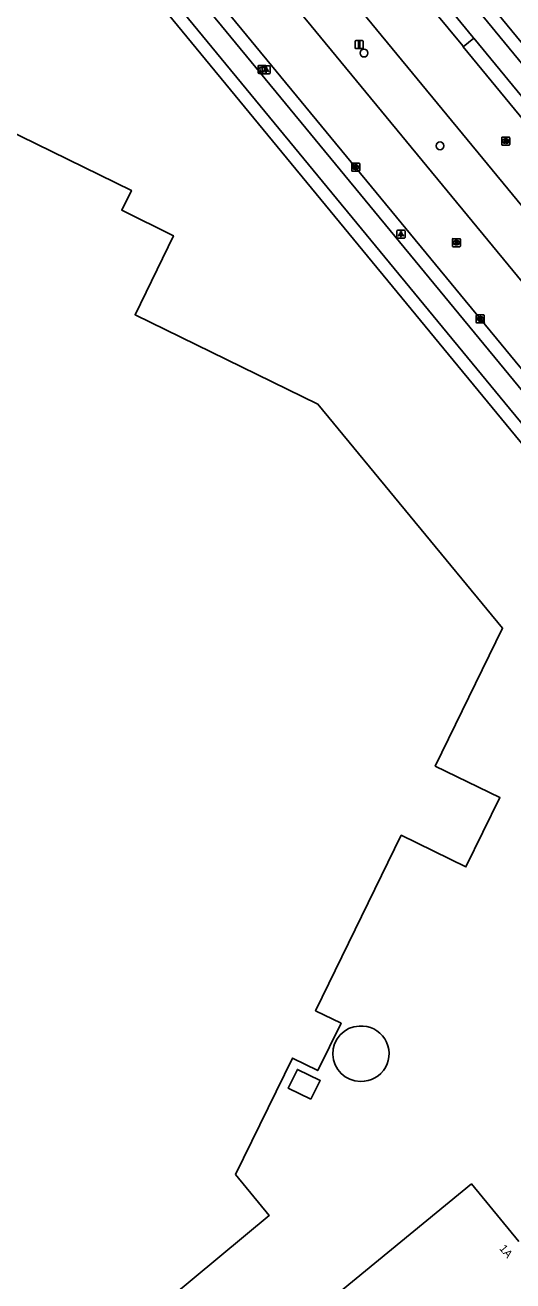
# Model space of a CAD drawing. Extents: x 156141 to 158132, y 385651 to 388399.
# Drawn here: x 156991.7 to 157052.6, y 386321.6 to 386478.5 of the extents above; entities that cross this region are included whole.
import ezdxf

# ---------------------------------------------------------------- set-up
doc = ezdxf.new("R2010")
doc.units = 0
for name, color, linetype in [('IMGEO_Afvalbak', 7, 'Continuous'), ('IMGEO_Boom', 7, 'Continuous'), ('IMGEO_Fietspad_gesloten', 7, 'Continuous'), ('IMGEO_Kolk', 7, 'Continuous'), ('IMGEO_Lage_trafo', 7, 'Continuous'), ('IMGEO_Lichtpunt', 7, 'Continuous'), ('IMGEO_Opslagtank', 7, 'Continuous'), ('IMGEO_Pand', 7, 'Continuous'), ('IMGEO_Pand_nummerreeks', 7, 'Continuous'), ('IMGEO_Rijbaan_lokaal_gesloten', 7, 'Continuous'), ('IMGEO_Rijbaan_lokaal_open', 7, 'Continuous'), ('IMGEO_Rioolput', 7, 'Continuous'), ('IMGEO_Verkeersbordpaal', 7, 'Continuous'), ('IMGEO_Voetpad_open', 7, 'Continuous')]:
    doc.layers.add(name, color=color, linetype=linetype)

msp = doc.modelspace()

# ---------------------------------------------------------------- linework, layer by layer
at = {"layer": 'IMGEO_Afvalbak'}
for p, q in [((157020.78, 386472.54), (157020.78, 386473.34)), ((157020.78, 386473.34), (157020.78, 386472.54)), ((157020.88, 386473.44), (157021.67, 386473.44)), ((157021.67, 386473.44), (157020.88, 386473.44)), ((157021.67, 386472.44), (157020.88, 386472.44)), ((157020.88, 386472.44), (157021.67, 386472.44)), ((157021.77, 386473.34), (157021.77, 386472.54)), ((157021.77, 386472.54), (157021.77, 386473.34))]:
    msp.add_line(p, q, dxfattribs=at)
msp.add_lwpolyline([(157020.92, 386473.16), (157021.63, 386473.16), (157021.48, 386472.69), (157021.07, 386472.69), (157020.92, 386473.16)], dxfattribs=at)
for centre, start, end in [((157020.88, 386473.34), 90, 180), ((157020.88, 386473.34), 90, 180), ((157020.88, 386472.54), 180, 270), ((157020.88, 386472.54), 180, 270), ((157021.67, 386473.34), 0, 90), ((157021.67, 386473.34), 360, 90), ((157021.67, 386472.54), 270, 0), ((157021.67, 386472.54), 270, 0)]:
    msp.add_arc(centre, 0.1, start, end, dxfattribs=at)
at = {"layer": 'IMGEO_Boom'}
for centre in [(157033.99, 386474.98), (157043.48, 386463.39)]:
    msp.add_circle(centre, 0.489, dxfattribs=at)
at = {"layer": 'IMGEO_Fietspad_gesloten'}
for points in [[(156997.23, 386501.52), (157000, 386498.06), (157086.19, 386393.38)], [(157084.09, 386391.8), (157000, 386493.95), (156995.15, 386499.84)], [(157106.12, 386409.97), (157048.25, 386480.29)], [(157047.71, 386476.84), (157104.91, 386407.31)]]:
    msp.add_lwpolyline(points, dxfattribs=at)
at = {"layer": 'IMGEO_Kolk'}
for p, q in [((157032.45, 386460.3), (157032.45, 386461.15)), ((157032.52, 386461.23), (157033.37, 386461.23)), ((157033.37, 386460.23), (157032.52, 386460.23)), ((157032.96, 386460.45), (157032.93, 386460.45)), ((157032.94, 386461.01), (157032.96, 386461.01)), ((157033.45, 386461.15), (157033.45, 386460.3)), ((157048.01, 386441.35), (157048.01, 386442.2)), ((157048.09, 386442.27), (157048.94, 386442.27)), ((157048.94, 386441.27), (157048.09, 386441.27)), ((157048.5, 386442.05), (157048.53, 386442.05)), ((157048.52, 386441.49), (157048.5, 386441.49)), ((157049.01, 386442.2), (157049.01, 386441.35))]:
    msp.add_line(p, q, dxfattribs=at)
for points in [[(157032.45, 386460.3), (157032.45, 386461.15)], [(157032.52, 386461.23), (157033.37, 386461.23)], [(157033.37, 386460.23), (157032.52, 386460.23)], [(157032.77, 386460.93), (157032.89, 386460.93), (157032.89, 386460.78), (157033.02, 386460.93), (157033.19, 386460.93), (157033.04, 386460.78), (157033.19, 386460.53), (157033.04, 386460.53), (157032.96, 386460.69), (157032.89, 386460.63), (157032.89, 386460.53), (157032.77, 386460.53), (157032.77, 386460.93)], [(157033.45, 386461.15), (157033.45, 386460.3)], [(157048.01, 386441.35), (157048.01, 386442.2)], [(157048.09, 386442.27), (157048.94, 386442.27)], [(157048.94, 386441.27), (157048.09, 386441.27)], [(157048.33, 386441.97), (157048.46, 386441.97), (157048.46, 386441.82), (157048.59, 386441.97), (157048.75, 386441.97), (157048.61, 386441.82), (157048.76, 386441.57), (157048.61, 386441.57), (157048.52, 386441.74), (157048.46, 386441.67), (157048.46, 386441.57), (157048.33, 386441.57), (157048.33, 386441.97)], [(157049.01, 386442.2), (157049.01, 386441.35)]]:
    msp.add_lwpolyline(points, dxfattribs=at)
for centre, start, end in [((157032.52, 386461.15), 91.552, 178.448), ((157032.52, 386461.15), 91.552, 178.448), ((157032.52, 386460.3), 181.552, 268.448), ((157032.52, 386460.3), 181.552, 268.448), ((157033.37, 386461.15), 1.552, 88.448), ((157033.37, 386461.15), 1.552, 88.448), ((157033.37, 386460.3), 271.552, 358.448), ((157033.37, 386460.3), 271.552, 358.448), ((157048.09, 386442.2), 91.552, 178.448), ((157048.09, 386442.2), 91.552, 178.448), ((157048.09, 386441.35), 181.552, 268.448), ((157048.09, 386441.35), 181.552, 268.448), ((157048.94, 386442.2), 1.552, 88.448), ((157048.94, 386442.2), 1.552, 88.448), ((157048.94, 386441.35), 271.552, 358.448), ((157048.94, 386441.35), 271.552, 358.448)]:
    msp.add_arc(centre, 0.0765, start, end, dxfattribs=at)
for centre, major_axis, ratio, start_param, end_param in [((157032.93, 386460.73), (-0.387, 0.002), 0.722429, 4.712389, 7.853982), ((157032.96, 386460.73), (-0.39, 0.002), 0.717154, 1.570796, 4.712389), ((157048.5, 386441.77), (-0.387, 0.002), 0.722429, 4.712389, 7.853982), ((157048.52, 386441.77), (-0.39, 0.002), 0.717154, 1.570796, 4.712389)]:
    msp.add_ellipse(centre, major_axis=major_axis, ratio=ratio, start_param=start_param, end_param=end_param, dxfattribs=at)
at = {"layer": 'IMGEO_Lage_trafo'}
msp.add_lwpolyline([(157027.37, 386344.27), (157024.53, 386345.66), (157025.68, 386348.01), (157028.52, 386346.61), (157027.37, 386344.27)], dxfattribs=at)
at = {"layer": 'IMGEO_Lichtpunt'}
for p, q in [((157021.27, 386473.29), (157021.27, 386472.48)), ((157021.27, 386473.29), (157021.27, 386472.48)), ((157022.17, 386473.38), (157021.36, 386473.38)), ((157022.17, 386473.38), (157021.36, 386473.38)), ((157021.36, 386472.39), (157022.17, 386472.39)), ((157021.36, 386472.39), (157022.17, 386472.39)), ((157022.27, 386472.48), (157022.27, 386473.29)), ((157022.27, 386472.48), (157022.27, 386473.29)), ((157038.11, 386452.76), (157038.11, 386451.95)), ((157038.11, 386452.76), (157038.11, 386451.95)), ((157039.01, 386452.86), (157038.2, 386452.86)), ((157039.01, 386452.86), (157038.2, 386452.86)), ((157039.11, 386451.95), (157039.11, 386452.76)), ((157039.11, 386451.95), (157039.11, 386452.76)), ((157038.2, 386451.86), (157039.01, 386451.86)), ((157038.2, 386451.86), (157039.01, 386451.86))]:
    msp.add_line(p, q, dxfattribs=at)
for points in [[(157021.64, 386472.95), (157021.68, 386472.92), (157021.49, 386472.66), (157021.46, 386472.69), (157021.64, 386472.95)], [(157021.74, 386472.9), (157021.79, 386472.9), (157021.79, 386472.58), (157021.74, 386472.58), (157021.74, 386472.9)], [(157021.85, 386472.92), (157021.89, 386472.95), (157022.08, 386472.69), (157022.04, 386472.66), (157021.85, 386472.92)], [(157038.48, 386452.42), (157038.52, 386452.4), (157038.33, 386452.13), (157038.3, 386452.16), (157038.48, 386452.42)], [(157038.58, 386452.38), (157038.63, 386452.38), (157038.63, 386452.05), (157038.58, 386452.05), (157038.58, 386452.38)], [(157038.69, 386452.4), (157038.73, 386452.42), (157038.92, 386452.16), (157038.88, 386452.13), (157038.69, 386452.4)]]:
    msp.add_lwpolyline(points, dxfattribs=at)
for centre in [(157021.77, 386473.09), (157038.61, 386452.56)]:
    msp.add_circle(centre, 0.0994, dxfattribs=at)
for centre, start, end in [((157021.36, 386473.29), 90, 180), ((157021.36, 386473.29), 90, 180), ((157021.36, 386472.48), 180, 270), ((157021.36, 386472.48), 180, 270), ((157022.17, 386473.29), 0, 90), ((157022.17, 386473.29), 0, 90), ((157022.17, 386472.48), 270, 0), ((157022.17, 386472.48), 270, 360), ((157038.2, 386452.76), 90, 180), ((157038.2, 386452.76), 90, 180), ((157039.01, 386452.76), 0, 90), ((157039.01, 386452.76), 0, 90), ((157038.2, 386451.95), 180, 270), ((157038.2, 386451.95), 180, 270), ((157039.01, 386451.95), 270, 0), ((157039.01, 386451.95), 270, 360)]:
    msp.add_arc(centre, 0.0946, start, end, dxfattribs=at)
at = {"layer": 'IMGEO_Opslagtank'}
for centre, start, end in [((157033.55, 386349.97), 92.7, 270.0014), ((157033.67, 386349.97), 268.0657, 94.6357)]:
    msp.add_arc(centre, 3.46, start, end, dxfattribs=at)
at = {"layer": 'IMGEO_Pand'}
for points in [[(156967.17, 386476.28), (157004.95, 386457.81), (157003.75, 386455.35), (157010.2, 386452.15), (157005.4, 386442.29), (157028.24, 386431.13), (157051.3, 386403.13), (157042.88, 386385.91), (157050.96, 386381.96), (157046.72, 386373.3), (157038.65, 386377.25), (157027.94, 386355.34), (157031.12, 386353.77), (157028.21, 386347.87), (157025.05, 386349.43), (157017.94, 386334.89)], [(157017.94, 386334.89), (157022.13, 386329.74), (156975.52, 386291.04)], [(156998.63, 386281.54), (156988.88, 386285.67), (157047.4, 386333.71), (157053.34, 386326.49)]]:
    msp.add_lwpolyline(points, dxfattribs=at)
at = {"layer": 'IMGEO_Rijbaan_lokaal_gesloten'}
for points in [[(157109.73, 386387.85), (157107.76, 386390.26), (157017.39, 386500), (157006.88, 386512.77)], [(157002.33, 386508.86), (157009.63, 386500), (157103.14, 386386.43), (157105.1, 386384.05)], [(157099.71, 386379.64), (157000.59, 386500), (157000, 386500.71), (156999.31, 386501.55)], [(157046.39, 386475.77), (157046.31, 386475.87), (157038.8, 386485)], [(157115.11, 386392.27), (157046.39, 386475.77)]]:
    msp.add_lwpolyline(points, dxfattribs=at)
at = {"layer": 'IMGEO_Rijbaan_lokaal_open'}
for points in [[(157040.11, 386486.1), (157047.63, 386476.93), (157047.71, 386476.84)], [(157046.39, 386475.77), (157047.71, 386476.84)]]:
    msp.add_lwpolyline(points, dxfattribs=at)
at = {"layer": 'IMGEO_Rioolput'}
for p, q in [((157051.19, 386463.56), (157051.19, 386464.41)), ((157051.27, 386464.48), (157052.12, 386464.48)), ((157052.12, 386463.48), (157051.27, 386463.48)), ((157051.68, 386464.26), (157051.71, 386464.26)), ((157051.7, 386463.7), (157051.68, 386463.7)), ((157052.19, 386464.41), (157052.19, 386463.56)), ((157045.03, 386450.87), (157045.03, 386451.72)), ((157045.1, 386451.79), (157045.96, 386451.79)), ((157045.96, 386450.79), (157045.1, 386450.79)), ((157045.54, 386451.01), (157045.51, 386451.01)), ((157045.52, 386451.57), (157045.54, 386451.57)), ((157046.03, 386451.72), (157046.03, 386450.87))]:
    msp.add_line(p, q, dxfattribs=at)
for points in [[(157051.19, 386463.56), (157051.19, 386464.41)], [(157051.27, 386464.48), (157052.12, 386464.48)], [(157052.12, 386463.48), (157051.27, 386463.48)], [(157051.78, 386464.18), (157051.53, 386464.18), (157051.53, 386463.78)], [(157051.53, 386463.78), (157051.65, 386463.78), (157051.65, 386463.94), (157051.67, 386463.94)], [(157051.71, 386464.1), (157051.65, 386464.1), (157051.65, 386464.02)], [(157051.65, 386464.02), (157051.71, 386464.02)], [(157051.71, 386463.91), (157051.78, 386463.78), (157051.92, 386463.78), (157051.86, 386463.91)], [(157052.19, 386464.41), (157052.19, 386463.56)], [(157045.03, 386450.87), (157045.03, 386451.72)], [(157045.1, 386451.79), (157045.96, 386451.79)], [(157045.96, 386450.79), (157045.1, 386450.79)], [(157045.62, 386451.49), (157045.37, 386451.49), (157045.37, 386451.09)], [(157045.37, 386451.09), (157045.49, 386451.09), (157045.49, 386451.26), (157045.5, 386451.26)], [(157045.54, 386451.41), (157045.49, 386451.41), (157045.49, 386451.33)], [(157045.49, 386451.33), (157045.54, 386451.33)], [(157045.55, 386451.23), (157045.62, 386451.09), (157045.76, 386451.09), (157045.69, 386451.22)], [(157046.03, 386451.72), (157046.03, 386450.87)]]:
    msp.add_lwpolyline(points, dxfattribs=at)
for centre, radius, start, end in [((157051.27, 386464.41), 0.0765, 91.552, 178.448), ((157051.27, 386464.41), 0.0765, 91.552, 178.448), ((157051.27, 386463.56), 0.0765, 181.552, 268.448), ((157051.27, 386463.56), 0.0765, 181.552, 268.448), ((157051.66, 386463.89), 0.0533, 26.0293, 88.6989), ((157051.71, 386464), 0.0964, 77.0061, 93.1865), ((157051.69, 386464.21), 0.19, 274.7715, 282.9687), ((157051.73, 386464.06), 0.0378, 276.6634, 79.6772), ((157051.78, 386464.07), 0.109, 350.3612, 89.416), ((157051.78, 386464.07), 0.112, 277.5842, 350.9817), ((157051.76, 386463.85), 0.108, 29.5134, 73.7905), ((157052.12, 386464.41), 0.0765, 1.552, 88.448), ((157052.12, 386464.41), 0.0765, 1.552, 88.448), ((157052.12, 386463.56), 0.0765, 271.552, 358.448), ((157052.12, 386463.56), 0.0765, 271.552, 358.448), ((157045.11, 386451.72), 0.0765, 91.552, 178.448), ((157045.11, 386451.72), 0.0765, 91.552, 178.448), ((157045.11, 386450.87), 0.0765, 181.552, 268.448), ((157045.11, 386450.87), 0.0765, 181.552, 268.448), ((157045.5, 386451.2), 0.0533, 26.0293, 88.6989), ((157045.55, 386451.32), 0.0964, 77.0061, 93.1865), ((157045.53, 386451.52), 0.19, 274.7715, 282.9687), ((157045.56, 386451.37), 0.0378, 276.6634, 79.6772), ((157045.62, 386451.38), 0.109, 350.3612, 89.416), ((157045.62, 386451.38), 0.112, 277.5842, 350.9817), ((157045.6, 386451.17), 0.108, 29.5134, 73.7905), ((157045.95, 386451.72), 0.0765, 1.552, 88.448), ((157045.95, 386451.72), 0.0765, 1.552, 88.448), ((157045.95, 386450.87), 0.0765, 271.552, 358.448), ((157045.95, 386450.87), 0.0765, 271.552, 358.448)]:
    msp.add_arc(centre, radius, start, end, dxfattribs=at)
for centre, major_axis, ratio, start_param, end_param in [((157051.68, 386463.98), (-0.387, 0.002), 0.722429, 4.712389, 7.853982), ((157051.7, 386463.98), (-0.39, 0.002), 0.717154, 1.570796, 4.712389), ((157045.52, 386451.29), (-0.387, 0.002), 0.722429, 4.712389, 7.853982), ((157045.54, 386451.29), (-0.39, 0.002), 0.717154, 1.570796, 4.712389)]:
    msp.add_ellipse(centre, major_axis=major_axis, ratio=ratio, start_param=start_param, end_param=end_param, dxfattribs=at)
at = {"layer": 'IMGEO_Verkeersbordpaal'}
for p, q in [((157032.88, 386475.64), (157032.88, 386476.44)), ((157032.88, 386476.44), (157032.88, 386475.64)), ((157032.98, 386476.54), (157033.77, 386476.54)), ((157033.77, 386476.54), (157032.98, 386476.54)), ((157033.77, 386475.54), (157032.98, 386475.54)), ((157032.98, 386475.54), (157033.77, 386475.54)), ((157033.87, 386476.44), (157033.87, 386475.64)), ((157033.87, 386475.64), (157033.87, 386476.44))]:
    msp.add_line(p, q, dxfattribs=at)
msp.add_lwpolyline([(157033.3, 386476.42), (157033.45, 386476.42), (157033.45, 386475.67), (157033.3, 386475.67), (157033.3, 386476.42)], dxfattribs=at)
for centre, start, end in [((157032.98, 386476.44), 90, 180), ((157032.98, 386476.44), 90, 180), ((157032.98, 386475.64), 180, 270), ((157032.98, 386475.64), 180, 270), ((157033.77, 386476.44), 0, 90), ((157033.77, 386476.44), 360, 90), ((157033.77, 386475.64), 270, 0), ((157033.77, 386475.64), 270, 0)]:
    msp.add_arc(centre, 0.1, start, end, dxfattribs=at)
at = {"layer": 'IMGEO_Voetpad_open'}
for points in [[(156993.9, 386498.84), (157000, 386491.44), (157082.67, 386391)], [(157049.53, 386481.28), (157107.84, 386410.44)]]:
    msp.add_lwpolyline(points, dxfattribs=at)

# ---------------------------------------------------------------- texts
at = {"layer": 'IMGEO_Pand_nummerreeks'}
msp.add_text('1A', height=1, rotation=309.4307, dxfattribs=at).set_placement((157050.83, 386325.61))

doc.saveas('drawing.dxf')
